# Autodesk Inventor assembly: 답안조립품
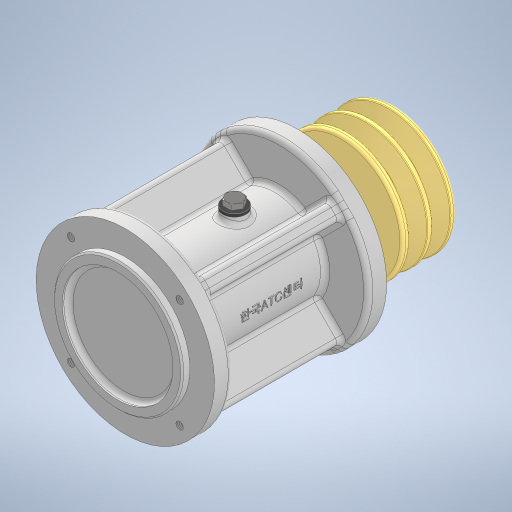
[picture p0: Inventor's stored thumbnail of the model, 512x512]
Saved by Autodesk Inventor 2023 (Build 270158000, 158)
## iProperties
Created: 2024-10
Part Number: 답안조립품
Document SubType Name: Assembly
Designer: home
Author: home
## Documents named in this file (18)
- C:\Users\home\Desktop\741004V1012\답안조립품.iam
- C:\Users\home\Desktop\741004V1012\본체.ipt
- C:\Users\home\Desktop\741004V1012\스러스트 볼베어링 512 02.ipt
- C:\Users\home\Desktop\741004V1012\어뎁터.ipt
- C:\Users\home\Desktop\741004V1012\육각 소켓 머리 볼트 M5x10.ipt
- C:\Users\home\Desktop\741004V1012\깊은 홈 볼베어링 6004.ipt
- C:\Users\home\Desktop\741004V1012\축.ipt
- C:\Users\home\Desktop\741004V1012\칼라.ipt
- C:\Users\home\Desktop\741004V1012\가스켓.ipt
- C:\Users\home\Desktop\741004V1012\커버.ipt
- C:\Users\home\Desktop\741004V1012\오일 실 20 35 8.ipt
- C:\Users\home\Desktop\741004V1012\실링 패드.ipt
- C:\Users\home\Desktop\741004V1012\육각 머리 볼트 M6x0.75x12.ipt
- C:\Users\home\Desktop\741004V1012\평행키 5x5x22.ipt
- C:\Users\home\Desktop\741004V1012\평와셔 M5.ipt
- C:\Users\home\Desktop\741004V1012\V 벨트 풀리.ipt
- C:\Users\home\Desktop\741004V1012\엔드캡.ipt
- C:\Users\home\Desktop\741004V1012\스프링와셔 M5.ipt
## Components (2 placed, 2 different names)
1. 가스켓:1
2. V 벨트 풀리:1
